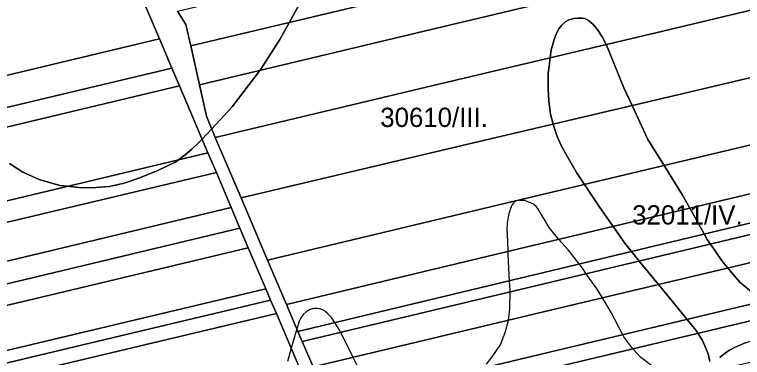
# Model space of a CAD drawing. Extents: x -521939 to -516426, y -1197857 to -1189551.
# Drawn here: x -521391 to -520825, y -1191463 to -1191197 of the extents above; entities that cross this region are included whole.
import ezdxf

# ---------------------------------------------------------------- set-up
doc = ezdxf.new("R2010")
doc.units = 0
for name, color, linetype in [('95560013', 7, 'Continuous'), ('95640013', 7, 'Continuous'), ('95660013', 7, 'Continuous')]:
    doc.layers.add(name, color=color, linetype=linetype)

msp = doc.modelspace()

# ---------------------------------------------------------------- linework, layer by layer
at = {"layer": '95560013'}
for points in [[(-520812.23, -1191086.24), (-520805.2, -1191114.16), (-520903.8, -1191137.67), (-521078.73, -1191179.38), (-521253.66, -1191221.09), (-521257.44, -1191204.41), (-521264.02, -1191194.06), (-521089.12, -1191152.32), (-520915.1, -1191110.79)], [(-520805.2, -1191114.16), (-520797.61, -1191144.17), (-520897.63, -1191168.05), (-521072.33, -1191209.76), (-521247.03, -1191251.47), (-521253.66, -1191221.09), (-521078.73, -1191179.38), (-520903.8, -1191137.67)], [(-520797.61, -1191144.17), (-520786.96, -1191185.86), (-520886.83, -1191209.61), (-521059.91, -1191250.77), (-521234.63, -1191292.32), (-521241.56, -1191275.78), (-521247.03, -1191251.47), (-521072.33, -1191209.76), (-520897.63, -1191168.05)], [(-521632.86, -1191283.41), (-521649.4, -1191246.83), (-521300.29, -1191163.2), (-521277.99, -1191215.69), (-521624.98, -1191298.54)], [(-520786.96, -1191185.86), (-520774.39, -1191235.28), (-520865.22, -1191256.77), (-521038.3, -1191297.72), (-521214.55, -1191339.42), (-521234.63, -1191292.32), (-521059.91, -1191250.77), (-520886.83, -1191209.61)], [(-521624.98, -1191298.54), (-521277.99, -1191215.69), (-521268.33, -1191238.36), (-521440.8, -1191279.42), (-521613.69, -1191320.58)], [(-521268.33, -1191238.36), (-521262.5, -1191252.21), (-521432.83, -1191292.83), (-521606.85, -1191334.33), (-521613.69, -1191320.58), (-521440.8, -1191279.42)], [(-520774.39, -1191235.28), (-520762.01, -1191284.51), (-520845.49, -1191304.49), (-521019.72, -1191346.19), (-521193.95, -1191387.89), (-521214.55, -1191339.42), (-521038.3, -1191297.72), (-520865.22, -1191256.77)], [(-521262.5, -1191252.21), (-521240.42, -1191304.4), (-521406.58, -1191344.01), (-521580.92, -1191385.57), (-521606.85, -1191334.33), (-521432.83, -1191292.83)], [(-521193.95, -1191387.89), (-521019.72, -1191346.19), (-520845.49, -1191304.49), (-520762.01, -1191284.51), (-520752.93, -1191320.48), (-520828.77, -1191338.58), (-521004.04, -1191380.41), (-521179.31, -1191422.24)], [(-521580.92, -1191385.57), (-521406.58, -1191344.01), (-521240.42, -1191304.4), (-521233.83, -1191319.62), (-521396.11, -1191358.32), (-521573.36, -1191400.59)], [(-521233.83, -1191319.62), (-521222.21, -1191346.98), (-521366.09, -1191381.3), (-521559.9, -1191427.53), (-521573.36, -1191400.59), (-521396.11, -1191358.32)], [(-521179.31, -1191422.24), (-521004.04, -1191380.41), (-520828.77, -1191338.58), (-520752.93, -1191320.48), (-520747.53, -1191341.72), (-520824.69, -1191360.25), (-520997.54, -1191401.76), (-521170.39, -1191443.27)], [(-520747.53, -1191341.72), (-520745.31, -1191350.43), (-520817.57, -1191367.67), (-520992.31, -1191409.36), (-521167.05, -1191451.05), (-521170.39, -1191443.27), (-520997.54, -1191401.76), (-520824.69, -1191360.25)], [(-521222.21, -1191346.98), (-521215.47, -1191362.92), (-521378.11, -1191401.74), (-521552.02, -1191443.25), (-521559.9, -1191427.53), (-521366.09, -1191381.3)], [(-521167.05, -1191451.05), (-520992.31, -1191409.36), (-520817.57, -1191367.67), (-520745.31, -1191350.43), (-520740.08, -1191370.95), (-520800.63, -1191385.4), (-520979.64, -1191428.12), (-521158.65, -1191470.84)], [(-521215.47, -1191362.92), (-521209, -1191378.24), (-521368.75, -1191416.29), (-521544.58, -1191458.17), (-521552.02, -1191443.25), (-521378.11, -1191401.74)], [(-521158.65, -1191470.84), (-520979.64, -1191428.12), (-520800.63, -1191385.4), (-520740.08, -1191370.95), (-520732.39, -1191401.49), (-520795.47, -1191416.55), (-520969.38, -1191458.07), (-521146.18, -1191500.28)], [(-521209, -1191378.24), (-521195.36, -1191410.11), (-521360.96, -1191449.54), (-521528.87, -1191489.52), (-521544.58, -1191458.17), (-521368.75, -1191416.29)], [(-520732.39, -1191401.49), (-520729.17, -1191413.61), (-520793.77, -1191429.02), (-520967.49, -1191470.46), (-521141.21, -1191511.9), (-521146.18, -1191500.28), (-520969.38, -1191458.07), (-520795.47, -1191416.55)], [(-521528.87, -1191489.52), (-521360.96, -1191449.54), (-521195.36, -1191410.11), (-521191.65, -1191418.82), (-521348.51, -1191456.23), (-521524.49, -1191498.2)], [(-521141.21, -1191511.9), (-520967.49, -1191470.46), (-520793.77, -1191429.02), (-520729.17, -1191413.61), (-520721.14, -1191444.12), (-520776.35, -1191457.3), (-520951.74, -1191499.17), (-521128.68, -1191541.41)], [(-521191.65, -1191418.82), (-521187.14, -1191429.23), (-521347.17, -1191467.37), (-521519.41, -1191508.42), (-521524.49, -1191498.2), (-521348.51, -1191456.23)], [(-521187.14, -1191429.23), (-521159.78, -1191493.6), (-521313.86, -1191530.4), (-521487.2, -1191571.8), (-521512.39, -1191522.49), (-521519.41, -1191508.42), (-521347.17, -1191467.37)]]:
    msp.add_lwpolyline(points, close=True, dxfattribs=at)
at = {"layer": '95640013'}
for points in [[(-521159.78, -1191493.6), (-521187.14, -1191429.23), (-521191.65, -1191418.82), (-521195.36, -1191410.11), (-521209, -1191378.24), (-521215.47, -1191362.92), (-521222.21, -1191346.98), (-521233.83, -1191319.62), (-521240.42, -1191304.4), (-521262.5, -1191252.21), (-521268.33, -1191238.36), (-521277.99, -1191215.69), (-521300.29, -1191163.2)], [(-521264.02, -1191194.06), (-521257.44, -1191204.41), (-521253.66, -1191221.09), (-521247.03, -1191251.47), (-521241.56, -1191275.78), (-521234.63, -1191292.32), (-521214.55, -1191339.42), (-521193.95, -1191387.89), (-521179.31, -1191422.24), (-521170.39, -1191443.27), (-521167.05, -1191451.05), (-521158.65, -1191470.84)]]:
    msp.add_lwpolyline(points, dxfattribs=at)
at = {"layer": '95660013'}
for points in [[(-521394.56, -1191312.57), (-521384.36, -1191319.3), (-521371.61, -1191325.09), (-521355.38, -1191329.73), (-521349.44, -1191330.39), (-521338.69, -1191331.58), (-521327.56, -1191331.35), (-521316.9, -1191330.42), (-521305.54, -1191327.87), (-521293.95, -1191324.16), (-521286.99, -1191321.29), (-521279.92, -1191318.37), (-521264.86, -1191311.01), (-521263.28, -1191309.85), (-521258.07, -1191306.02), (-521252.8, -1191301.44), (-521247.12, -1191296.11), (-521244.93, -1191293.74), (-521237.43, -1191285.63), (-521221.62, -1191268.53), (-521199.95, -1191240.23), (-521199.25, -1191239.32), (-521184.41, -1191216.13), (-521177.05, -1191202.82), (-521169.92, -1191189.94)], [(-521169.92, -1191189.94), (-521177.05, -1191202.82), (-521184.41, -1191216.13), (-521199.25, -1191239.32), (-521199.95, -1191240.23), (-521221.62, -1191268.53), (-521237.43, -1191285.63), (-521244.93, -1191293.74), (-521247.12, -1191296.11), (-521252.8, -1191301.44), (-521258.07, -1191306.02), (-521263.28, -1191309.85), (-521264.86, -1191311.01), (-521279.92, -1191318.37), (-521286.99, -1191321.29), (-521293.95, -1191324.16), (-521305.54, -1191327.87), (-521316.9, -1191330.42), (-521327.56, -1191331.35), (-521338.69, -1191331.58), (-521349.44, -1191330.39), (-521355.38, -1191329.73), (-521371.61, -1191325.09), (-521384.36, -1191319.3), (-521394.56, -1191312.57)], [(-520817.89, -1191412.47), (-520826.7, -1191405.29), (-520833.3, -1191397.4), (-520836.24, -1191393.9), (-520839.91, -1191389.52), (-520849.68, -1191375.33), (-520852.2, -1191371.67), (-520854.58, -1191367.43), (-520865.8, -1191347.42), (-520871.44, -1191337.36), (-520885.84, -1191314.15), (-520898.33, -1191294.01), (-520910.66, -1191267.52), (-520917.11, -1191253.68), (-520929.18, -1191223.61), (-520930.93, -1191220.1), (-520933.93, -1191214.11), (-520937.87, -1191208.19), (-520941.23, -1191204.14), (-520944.59, -1191201.36), (-520947.49, -1191199.96), (-520949.58, -1191199.5), (-520952.94, -1191199.5), (-520955.95, -1191199.85), (-520959.78, -1191201.01), (-520962.56, -1191202.51), (-520965.23, -1191204.95), (-520967.66, -1191207.85), (-520969.51, -1191211.32), (-520971.25, -1191216.08), (-520972.29, -1191219.91), (-520973.46, -1191224.19), (-520974.32, -1191230.42), (-520974.5, -1191231.72), (-520974.9, -1191235.15), (-520975.77, -1191242.5), (-520975.89, -1191248.47), (-520976.01, -1191254.56), (-520975.43, -1191264.06), (-520974.86, -1191268.28), (-520974.03, -1191274.38), (-520972.11, -1191282.06), (-520972.06, -1191282.26), (-520968.93, -1191291.65), (-520965.34, -1191299.76), (-520953.97, -1191319.51), (-520947.65, -1191328.94), (-520935.65, -1191346.87), (-520925.43, -1191361.65), (-520916.41, -1191374.69), (-520911.22, -1191381.03), (-520905.06, -1191388.54), (-520890.13, -1191406.76), (-520881.64, -1191417.11), (-520869.12, -1191432.41), (-520867.95, -1191433.85), (-520861.24, -1191442.15), (-520859.53, -1191444.71), (-520856.14, -1191449.8), (-520854.05, -1191454.43), (-520851.5, -1191460.69), (-520850.34, -1191466.72)], [(-520850.34, -1191466.72), (-520851.5, -1191460.69), (-520854.05, -1191454.43), (-520856.14, -1191449.8), (-520859.53, -1191444.71), (-520861.24, -1191442.15), (-520867.95, -1191433.85), (-520869.12, -1191432.41), (-520881.64, -1191417.11), (-520890.13, -1191406.76), (-520905.06, -1191388.54), (-520911.22, -1191381.03), (-520916.41, -1191374.69), (-520925.43, -1191361.65), (-520935.65, -1191346.87), (-520947.65, -1191328.94), (-520953.97, -1191319.51), (-520965.34, -1191299.76), (-520968.93, -1191291.65), (-520972.06, -1191282.26), (-520972.11, -1191282.06), (-520974.03, -1191274.38), (-520974.86, -1191268.28), (-520975.43, -1191264.06), (-520976.01, -1191254.56), (-520975.89, -1191248.47), (-520975.77, -1191242.5), (-520974.9, -1191235.15), (-520974.5, -1191231.72), (-520974.32, -1191230.42), (-520973.46, -1191224.19), (-520972.29, -1191219.91), (-520971.25, -1191216.08), (-520969.51, -1191211.32), (-520967.66, -1191207.85), (-520965.23, -1191204.95), (-520962.56, -1191202.51), (-520959.78, -1191201.01), (-520955.95, -1191199.85), (-520952.94, -1191199.5), (-520949.58, -1191199.5), (-520947.49, -1191199.96), (-520944.59, -1191201.36), (-520941.23, -1191204.14), (-520937.87, -1191208.19), (-520933.93, -1191214.11), (-520930.93, -1191220.1), (-520929.18, -1191223.61), (-520917.11, -1191253.68), (-520910.66, -1191267.52), (-520898.33, -1191294.01), (-520885.84, -1191314.15), (-520871.44, -1191337.36), (-520865.8, -1191347.42), (-520854.58, -1191367.43), (-520852.2, -1191371.67), (-520849.68, -1191375.33), (-520839.91, -1191389.52), (-520836.24, -1191393.9), (-520833.3, -1191397.4), (-520826.7, -1191405.29), (-520817.89, -1191412.47)], [(-520895.2, -1191469.97), (-520903.89, -1191463.47), (-520910.01, -1191456.75), (-520910.96, -1191455.71), (-520917.11, -1191447.36), (-520917.94, -1191445.79), (-520927.31, -1191428.01), (-520933.69, -1191417.15), (-520937.74, -1191410.27), (-520946.24, -1191398.37), (-520948.75, -1191394.85), (-520951.88, -1191390.77), (-520960.34, -1191379.73), (-520967.56, -1191371.7), (-520968.63, -1191370.51), (-520975.06, -1191362.46), (-520978.57, -1191356.68), (-520980.51, -1191353.47), (-520983.87, -1191347.68), (-520985.32, -1191346), (-520987.35, -1191344.32), (-520990.94, -1191342.64), (-520994.42, -1191341.48), (-520997.61, -1191341.3), (-520998.62, -1191341.42), (-520999.58, -1191341.54), (-521001.2, -1191342.06), (-521002.59, -1191343.1), (-521002.9, -1191343.47), (-521003.93, -1191344.72), (-521004.59, -1191346.25), (-521005.14, -1191347.51), (-521006.71, -1191352.84), (-521007.69, -1191358.98), (-521007.98, -1191363.67), (-521007.63, -1191373.35), (-521007.35, -1191381.2), (-521007.29, -1191382.92), (-521006.65, -1191394.03), (-521006.09, -1191403.81), (-521005.66, -1191411.43), (-521005.69, -1191412.55), (-521006.01, -1191425.69), (-521007.03, -1191434.66), (-521007.06, -1191434.96), (-521009.61, -1191444.23), (-521012.97, -1191453.16), (-521019.69, -1191463.13), (-521024.21, -1191468.69)], [(-520895.2, -1191469.97), (-520903.89, -1191463.47), (-520910.01, -1191456.75), (-520910.96, -1191455.71), (-520917.11, -1191447.36), (-520917.94, -1191445.79), (-520927.31, -1191428.01), (-520933.69, -1191417.15), (-520937.74, -1191410.27), (-520946.24, -1191398.37), (-520948.75, -1191394.85), (-520951.88, -1191390.77), (-520960.34, -1191379.73), (-520967.56, -1191371.7), (-520968.63, -1191370.51), (-520975.06, -1191362.46), (-520978.57, -1191356.68), (-520980.51, -1191353.47), (-520983.87, -1191347.68), (-520985.32, -1191346), (-520987.35, -1191344.32), (-520990.94, -1191342.64), (-520994.42, -1191341.48), (-520997.61, -1191341.3), (-520998.62, -1191341.42), (-520999.58, -1191341.54), (-521001.2, -1191342.06), (-521002.59, -1191343.1), (-521002.9, -1191343.47), (-521003.93, -1191344.72), (-521004.59, -1191346.25), (-521005.14, -1191347.51), (-521006.71, -1191352.84), (-521007.69, -1191358.98), (-521007.98, -1191363.67), (-521007.63, -1191373.35), (-521007.35, -1191381.2), (-521007.29, -1191382.92), (-521006.65, -1191394.03), (-521006.09, -1191403.81), (-521005.66, -1191411.43), (-521005.69, -1191412.55), (-521006.01, -1191425.69), (-521007.03, -1191434.66), (-521007.06, -1191434.96), (-521009.61, -1191444.23), (-521012.97, -1191453.16), (-521019.69, -1191463.13), (-521024.21, -1191468.69)], [(-521123.34, -1191471.94), (-521127.56, -1191463.42), (-521128.11, -1191462.3), (-521137.19, -1191443.93), (-521138.3, -1191441.68), (-521141.68, -1191436.38), (-521144.21, -1191432.41), (-521147.57, -1191428.93), (-521149.15, -1191427.78), (-521150.12, -1191427.08), (-521153.02, -1191425.8), (-521155.33, -1191425.34), (-521158, -1191425.34), (-521161.01, -1191426.27), (-521164.03, -1191428.01), (-521166.23, -1191429.98), (-521168.2, -1191432.76), (-521169.48, -1191435.31), (-521171.23, -1191441.29), (-521175.62, -1191456.32), (-521178.63, -1191466.6)], [(-521123.34, -1191471.94), (-521127.56, -1191463.42), (-521128.11, -1191462.3), (-521137.19, -1191443.93), (-521138.3, -1191441.68), (-521141.68, -1191436.38), (-521144.21, -1191432.41), (-521147.57, -1191428.93), (-521149.15, -1191427.78), (-521150.12, -1191427.08), (-521153.02, -1191425.8), (-521155.33, -1191425.34), (-521158, -1191425.34), (-521161.01, -1191426.27), (-521164.03, -1191428.01), (-521166.23, -1191429.98), (-521168.2, -1191432.76), (-521169.48, -1191435.31), (-521171.23, -1191441.29), (-521175.62, -1191456.32), (-521178.63, -1191466.6)], [(-520842.34, -1191463.59), (-520840.43, -1191461.74), (-520837.32, -1191459.5), (-520835.45, -1191458.14), (-520833.31, -1191456.96), (-520831.04, -1191455.71), (-520822.81, -1191452), (-520809.02, -1191447.83), (-520804.04, -1191446.32), (-520791.4, -1191444.12), (-520777.96, -1191442.38), (-520768.8, -1191441.91), (-520759.53, -1191442.61), (-520745.97, -1191445.04), (-520736.23, -1191447.71), (-520727.65, -1191450.61), (-520722.2, -1191454.09), (-520717.06, -1191458.67), (-520716.87, -1191458.84), (-520711.19, -1191465.44)], [(-520822.81, -1191452), (-520831.04, -1191455.71), (-520833.31, -1191456.96), (-520835.45, -1191458.14), (-520837.32, -1191459.5), (-520840.43, -1191461.74), (-520842.34, -1191463.59)]]:
    msp.add_lwpolyline(points, dxfattribs=at)

# ---------------------------------------------------------------- texts
for s, rotation, p in [('30610/III.', 0, (-521106.41, -1191284.23)), ('32011/IV.', 360, (-520910.6, -1191360.11))]:
    msp.add_text(s, height=15, rotation=rotation, dxfattribs=at).set_placement(p)

doc.saveas('drawing.dxf')
